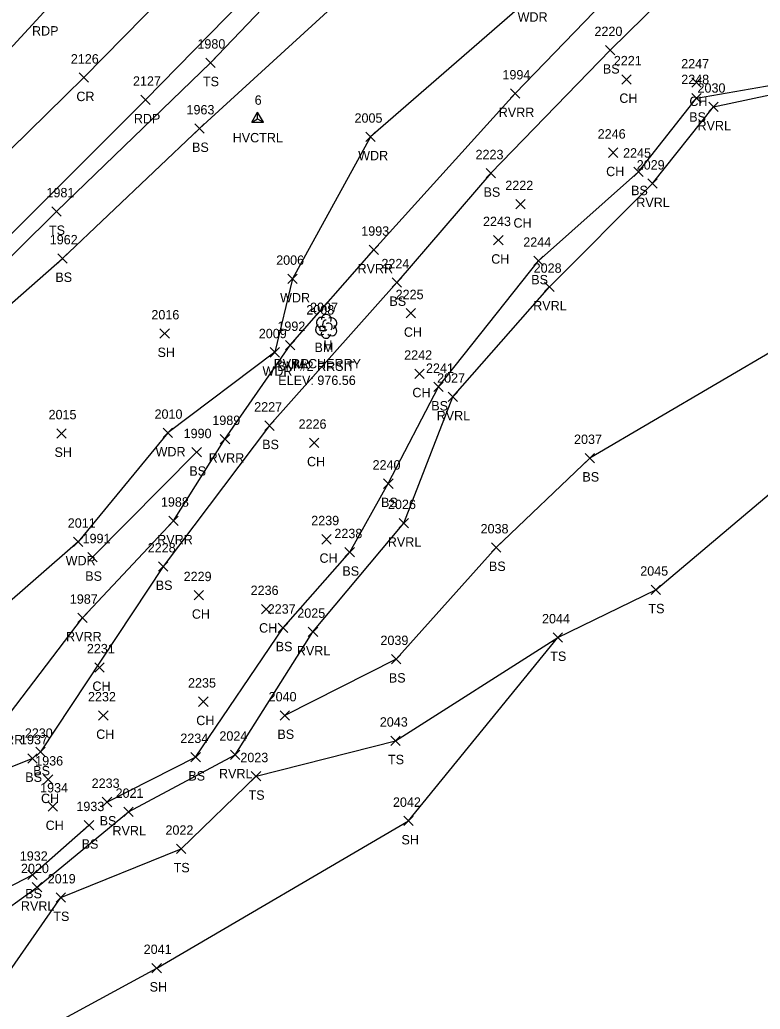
# Model space of a CAD drawing. Extents: x 1633660 to 1636532, y 388643 to 392631.
# Drawn here: x 1634615.1 to 1634772.8, y 388902.9 to 389113.6 of the extents above; entities that cross this region are included whole.
import ezdxf

# ---------------------------------------------------------------- set-up
doc = ezdxf.new("R2010")
doc.units = 0
for name, color, linetype in [('C_A', 7, 'Continuous'), ('C_C', 7, 'Continuous'), ('C_I', 7, 'Continuous'), ('CPBM', 7, 'Continuous'), ('CPSM', 7, 'Continuous'), ('L_A', 7, 'Continuous'), ('L_C', 7, 'Continuous'), ('L_I', 7, 'Continuous'), ('L_TIC', 7, 'Continuous'), ('LAWA', 7, 'Continuous'), ('LAWE', 7, 'Continuous'), ('LELB', 7, 'Continuous'), ('LSOGP', 7, 'Continuous'), ('LTD', 7, 'Continuous'), ('P_A', 7, 'Continuous'), ('P_I', 7, 'Continuous'), ('P_TIC', 7, 'Continuous'), ('PET', 7, 'Continuous'), ('PRC', 7, 'Continuous')]:
    doc.layers.add(name, color=color, linetype=linetype)

msp = doc.modelspace()

# ---------------------------------------------------------------- linework, layer by layer
at = {"layer": 'CPBM'}
for p, q in [((1634679.08, 389047.33), (1634679.08, 389048.33)), ((1634679.08, 389048.33), (1634680.08, 389048.33)), ((1634679.58, 389047.83), (1634679.58, 389047.83)), ((1634679.58, 389047.83), (1634679.58, 389047.83)), ((1634680.08, 389048.33), (1634680.08, 389047.33)), ((1634680.08, 389047.33), (1634679.08, 389047.33))]:
    msp.add_line(p, q, dxfattribs=at)
at = {"layer": 'CPSM'}
for p, q in [((1634664.53, 389091.76), (1634665.78, 389093.93)), ((1634667.03, 389091.76), (1634665.78, 389093.93)), ((1634665.79, 389092.49), (1634665.78, 389093.93)), ((1634664.53, 389091.76), (1634665.79, 389092.49)), ((1634664.53, 389091.76), (1634667.03, 389091.76)), ((1634665.79, 389092.49), (1634665.79, 389092.49)), ((1634665.79, 389092.49), (1634667.03, 389091.76))]:
    msp.add_line(p, q, dxfattribs=at)
at = {"layer": 'L_TIC'}
for points in [[(1634739.89, 389106.13), (1634741.89, 389108.13)], [(1634741.89, 389106.13), (1634739.89, 389108.13)], [(1634654.74, 389103.45), (1634656.74, 389105.45)], [(1634656.74, 389103.45), (1634654.74, 389105.45)], [(1634743.35, 389099.89), (1634745.35, 389101.89)], [(1634745.35, 389099.89), (1634743.35, 389101.89)], [(1634758.27, 389099.23), (1634760.27, 389101.23)], [(1634760.27, 389099.23), (1634758.27, 389101.23)], [(1634719.63, 389096.89), (1634721.63, 389098.89)], [(1634721.63, 389096.89), (1634719.63, 389098.89)], [(1634758.28, 389095.89), (1634760.28, 389097.89)], [(1634760.28, 389095.89), (1634758.28, 389097.89)], [(1634761.92, 389094.06), (1634763.92, 389096.06)], [(1634763.92, 389094.06), (1634761.92, 389096.06)], [(1634652.38, 389089.44), (1634654.38, 389091.44)], [(1634654.38, 389089.44), (1634652.38, 389091.44)], [(1634688.85, 389087.67), (1634690.85, 389089.67)], [(1634690.85, 389087.67), (1634688.85, 389089.67)], [(1634740.55, 389084.29), (1634742.55, 389086.29)], [(1634742.55, 389084.29), (1634740.55, 389086.29)], [(1634714.47, 389079.9), (1634716.47, 389081.9)], [(1634716.47, 389079.9), (1634714.47, 389081.9)], [(1634745.9, 389080.24), (1634747.9, 389082.24)], [(1634747.9, 389080.24), (1634745.9, 389082.24)], [(1634748.89, 389077.7), (1634750.89, 389079.7)], [(1634750.89, 389077.7), (1634748.89, 389079.7)], [(1634720.81, 389073.33), (1634722.81, 389075.33)], [(1634722.81, 389073.33), (1634720.81, 389075.33)], [(1634621.93, 389071.78), (1634623.93, 389073.78)], [(1634623.93, 389071.78), (1634621.93, 389073.78)], [(1634716.06, 389065.66), (1634718.06, 389067.66)], [(1634718.06, 389065.66), (1634716.06, 389067.66)], [(1634689.56, 389063.6), (1634691.56, 389065.6)], [(1634691.56, 389063.6), (1634689.56, 389065.6)], [(1634623.25, 389061.77), (1634625.25, 389063.77)], [(1634625.25, 389061.77), (1634623.25, 389063.77)], [(1634724.63, 389061.25), (1634726.63, 389063.25)], [(1634726.63, 389061.25), (1634724.63, 389063.25)], [(1634672.22, 389057.41), (1634674.22, 389059.41)], [(1634674.22, 389057.41), (1634672.22, 389059.41)], [(1634694.42, 389056.67), (1634696.42, 389058.67)], [(1634696.42, 389056.67), (1634694.42, 389058.67)], [(1634726.93, 389055.72), (1634728.93, 389057.72)], [(1634728.93, 389055.72), (1634726.93, 389057.72)], [(1634697.45, 389050.09), (1634699.45, 389052.09)], [(1634699.45, 389050.09), (1634697.45, 389052.09)], [(1634644.99, 389045.78), (1634646.99, 389047.78)], [(1634646.99, 389045.78), (1634644.99, 389047.78)], [(1634671.7, 389043.33), (1634673.7, 389045.33)], [(1634673.7, 389043.33), (1634671.7, 389045.33)], [(1634668.47, 389041.78), (1634670.47, 389043.78)], [(1634670.47, 389041.78), (1634668.47, 389043.78)], [(1634699.27, 389037.21), (1634701.27, 389039.21)], [(1634701.27, 389037.21), (1634699.27, 389039.21)], [(1634703.34, 389034.4), (1634705.34, 389036.4)], [(1634705.34, 389034.4), (1634703.34, 389036.4)], [(1634706.36, 389032.31), (1634708.36, 389034.31)], [(1634708.36, 389032.31), (1634706.36, 389034.31)], [(1634623.03, 389024.52), (1634625.03, 389026.52)], [(1634625.03, 389024.52), (1634623.03, 389026.52)], [(1634645.69, 389024.62), (1634647.69, 389026.62)], [(1634647.69, 389024.62), (1634645.69, 389026.62)], [(1634667.32, 389026.16), (1634669.32, 389028.16)], [(1634669.32, 389026.16), (1634667.32, 389028.16)], [(1634657.84, 389023.3), (1634659.84, 389025.3)], [(1634659.84, 389023.3), (1634657.84, 389025.3)], [(1634676.82, 389022.51), (1634678.82, 389024.51)], [(1634678.82, 389022.51), (1634676.82, 389024.51)], [(1634651.8, 389020.5), (1634653.8, 389022.5)], [(1634653.8, 389020.5), (1634651.8, 389022.5)], [(1634735.53, 389019.26), (1634737.53, 389021.26)], [(1634737.53, 389019.26), (1634735.53, 389021.26)], [(1634692.63, 389013.81), (1634694.63, 389015.81)], [(1634694.63, 389013.81), (1634692.63, 389015.81)], [(1634646.88, 389005.91), (1634648.88, 389007.91)], [(1634648.88, 389005.91), (1634646.88, 389007.91)], [(1634695.95, 389005.4), (1634697.95, 389007.4)], [(1634697.95, 389005.4), (1634695.95, 389007.4)], [(1634626.54, 389001.43), (1634628.54, 389003.43)], [(1634628.54, 389001.43), (1634626.54, 389003.43)], [(1634679.48, 389001.96), (1634681.48, 389003.96)], [(1634681.48, 389001.96), (1634679.48, 389003.96)], [(1634684.4, 388999.21), (1634686.4, 389001.21)], [(1634686.4, 388999.21), (1634684.4, 389001.21)], [(1634715.62, 389000.22), (1634717.62, 389002.22)], [(1634717.62, 389000.22), (1634715.62, 389002.22)], [(1634629.63, 388998.13), (1634631.63, 389000.13)], [(1634631.63, 388998.13), (1634629.63, 389000.13)], [(1634644.64, 388996.18), (1634646.64, 388998.18)], [(1634646.64, 388996.18), (1634644.64, 388998.18)], [(1634749.63, 388991.22), (1634751.63, 388993.22)], [(1634751.63, 388991.22), (1634749.63, 388993.22)], [(1634652.29, 388990.05), (1634654.29, 388992.05)], [(1634654.29, 388990.05), (1634652.29, 388992.05)], [(1634666.61, 388987.1), (1634668.61, 388989.1)], [(1634668.61, 388987.1), (1634666.61, 388989.1)], [(1634627.48, 388985.24), (1634629.48, 388987.24)], [(1634629.48, 388985.24), (1634627.48, 388987.24)], [(1634670.2, 388983.13), (1634672.2, 388985.13)], [(1634672.2, 388983.13), (1634670.2, 388985.13)], [(1634676.58, 388982.24), (1634678.58, 388984.24)], [(1634678.58, 388982.24), (1634676.58, 388984.24)], [(1634728.71, 388981.06), (1634730.71, 388983.06)], [(1634730.71, 388981.06), (1634728.71, 388983.06)], [(1634694.3, 388976.45), (1634696.3, 388978.45)], [(1634696.3, 388976.45), (1634694.3, 388978.45)], [(1634631.12, 388974.68), (1634633.12, 388976.68)], [(1634633.12, 388974.68), (1634631.12, 388976.68)], [(1634653.23, 388967.39), (1634655.23, 388969.39)], [(1634655.23, 388967.39), (1634653.23, 388969.39)], [(1634631.92, 388964.45), (1634633.92, 388966.45)], [(1634633.92, 388964.45), (1634631.92, 388966.45)], [(1634670.56, 388964.45), (1634672.56, 388966.45)], [(1634672.56, 388964.45), (1634670.56, 388966.45)], [(1634694.16, 388959.07), (1634696.16, 388961.07)], [(1634696.16, 388959.07), (1634694.16, 388961.07)], [(1634616.86, 388955.31), (1634618.86, 388957.31)], [(1634618.86, 388955.31), (1634616.86, 388957.31)], [(1634618.55, 388956.69), (1634620.55, 388958.69)], [(1634620.55, 388956.69), (1634618.55, 388958.69)], [(1634651.59, 388955.59), (1634653.59, 388957.59)], [(1634653.59, 388955.59), (1634651.59, 388957.59)], [(1634659.99, 388956.08), (1634661.99, 388958.08)], [(1634661.99, 388956.08), (1634659.99, 388958.08)], [(1634620.16, 388950.79), (1634622.16, 388952.79)], [(1634622.16, 388950.79), (1634620.16, 388952.79)], [(1634664.45, 388951.5), (1634666.45, 388953.5)], [(1634666.45, 388951.5), (1634664.45, 388953.5)], [(1634621.15, 388945.06), (1634623.15, 388947.06)], [(1634623.15, 388945.06), (1634621.15, 388947.06)], [(1634632.7, 388946.02), (1634634.7, 388948.02)], [(1634634.7, 388946.02), (1634632.7, 388948.02)], [(1634637.3, 388943.91), (1634639.3, 388945.91)], [(1634639.3, 388943.91), (1634637.3, 388945.91)], [(1634628.87, 388941.08), (1634630.87, 388943.08)], [(1634630.87, 388941.08), (1634628.87, 388943.08)], [(1634696.95, 388941.99), (1634698.95, 388943.99)], [(1634698.95, 388941.99), (1634696.95, 388943.99)], [(1634648.49, 388936.05), (1634650.49, 388938.05)], [(1634650.49, 388936.05), (1634648.49, 388938.05)], [(1634616.83, 388930.52), (1634618.83, 388932.52)], [(1634618.83, 388930.52), (1634616.83, 388932.52)], [(1634617.8, 388927.88), (1634619.8, 388929.88)], [(1634619.8, 388927.88), (1634617.8, 388929.88)], [(1634622.86, 388925.68), (1634624.86, 388927.68)], [(1634624.86, 388925.68), (1634622.86, 388927.68)], [(1634643.29, 388910.66), (1634645.29, 388912.66)], [(1634645.29, 388910.66), (1634643.29, 388912.66)]]:
    msp.add_lwpolyline(points, dxfattribs=at)
at = {"layer": 'LAWA'}
msp.add_lwpolyline([(1634777.74, 389176.81), (1634754.17, 389147.84), (1634723.8, 389118.19), (1634689.85, 389088.67), (1634673.22, 389058.41), (1634669.47, 389042.78), (1634646.69, 389025.62), (1634627.54, 389002.43), (1634610.06, 388987.13), (1634597.62, 388969.61)], dxfattribs=at)
at = {"layer": 'LAWE'}
for points in [[(1634485.27, 388945.87), (1634504.2, 388941.24), (1634525.53, 388940.73), (1634548.51, 388932.94), (1634584.66, 388920), (1634598.75, 388914.41), (1634618.8, 388928.88), (1634638.3, 388944.91), (1634660.99, 388957.08), (1634677.58, 388983.24), (1634696.95, 389006.4), (1634707.36, 389033.31), (1634727.93, 389056.72), (1634749.89, 389078.7), (1634762.92, 389095.06), (1634797.9, 389102.54), (1634816.33, 389112.04), (1634824.18, 389130.77), (1634824.18, 389150.65), (1634818.45, 389174.95), (1634815.05, 389205.92), (1634802.11, 389220.82), (1634788.76, 389226.82)], [(1634520.43, 388972.83), (1634529.58, 388972.39), (1634557.27, 388957.37), (1634580.07, 388955.67), (1634596.48, 388954.83), (1634611.77, 388964.29), (1634628.48, 388986.24), (1634647.88, 389006.91), (1634658.84, 389024.3), (1634672.7, 389044.33), (1634690.56, 389064.6), (1634720.63, 389097.89), (1634743.8, 389121.88), (1634765.96, 389139.81), (1634789.88, 389159.93), (1634790.78, 389168.23), (1634779.52, 389189.43), (1634780.72, 389197.89), (1634770.08, 389207.77)]]:
    msp.add_lwpolyline(points, dxfattribs=at)
at = {"layer": 'LELB'}
for points in [[(1634633.7, 388947.02), (1634652.59, 388956.59), (1634671.2, 388984.13), (1634685.4, 389000.21), (1634693.63, 389014.81), (1634704.34, 389035.4), (1634725.63, 389062.25), (1634746.9, 389081.24), (1634759.28, 389096.89), (1634788.69, 389102.01), (1634810.12, 389114.6), (1634818.92, 389123.64), (1634818.09, 389148.69), (1634815.05, 389173.41), (1634811.19, 389202.43), (1634801.32, 389217.95), (1634788.87, 389224.41)], [(1634776.58, 389212.05), (1634784.35, 389200.64), (1634784.71, 389191.5), (1634794.51, 389166.3), (1634783.97, 389147.59), (1634762.83, 389128.67), (1634740.89, 389107.13), (1634715.47, 389080.9), (1634695.42, 389057.67), (1634668.32, 389027.16), (1634645.64, 388997.18), (1634619.55, 388957.69)], [(1634531.18, 388975.28), (1634550.04, 388993.84), (1634582.85, 389016.58), (1634590.99, 389033.59), (1634624.25, 389062.77), (1634653.38, 389090.44), (1634686.4, 389120.7), (1634717.26, 389150.25), (1634744.21, 389175.48), (1634771.92, 389200.56)], [(1634703.21, 389149.54), (1634682.53, 389132.47), (1634655.74, 389104.45), (1634622.93, 389072.78), (1634589.92, 389040.08), (1634578.99, 389022.4), (1634560.52, 389008.32), (1634535.52, 388993.05), (1634511.92, 388973.77)], [(1634814.97, 389105.53), (1634790.96, 389078.59), (1634778.32, 389060.05), (1634777.25, 389044.1), (1634736.53, 389020.26), (1634716.62, 389001.22), (1634695.3, 388977.45), (1634671.56, 388965.45)], [(1634609.99, 388906.9), (1634623.86, 388926.68), (1634649.49, 388937.05), (1634665.45, 388952.5), (1634695.16, 388960.07), (1634729.71, 388982.06), (1634750.63, 388992.22), (1634777.03, 389014.48), (1634810.97, 389037.99)], [(1634652.8, 389021.5), (1634630.63, 388999.13)], [(1634617.86, 388956.31), (1634597.1, 388947.99), (1634578.19, 388950.92), (1634563.38, 388953.01), (1634537.32, 388959.95), (1634518.55, 388966.68)], [(1634486.03, 388958.42), (1634504.06, 388945.03), (1634527.82, 388945.02), (1634547.83, 388937.52), (1634559.74, 388934.65), (1634574.19, 388927.83), (1634589.05, 388923.96), (1634604.77, 388924.76), (1634617.83, 388931.52), (1634629.87, 388942.08)]]:
    msp.add_lwpolyline(points, dxfattribs=at)
at = {"layer": 'LSOGP'}
msp.add_lwpolyline([(1634218.98, 388740.85), (1634254.67, 388740.24), (1634315.25, 388739.85), (1634380.93, 388763.62), (1634394.19, 388796.15), (1634428.1, 388811.92), (1634452.29, 388827.49), (1634483.59, 388839.11), (1634515.33, 388848.44), (1634546.28, 388863.72), (1634572.45, 388876.23), (1634604.94, 388890.27), (1634644.29, 388911.66), (1634697.95, 388942.99), (1634729.71, 388982.06), (1634750.63, 388992.22), (1634777.03, 389014.48), (1634810.97, 389037.99), (1634811.65, 389038.97), (1634835.21, 389072.38), (1634837.85, 389085.95), (1634849.33, 389112.53), (1634851.42, 389137.05)], dxfattribs=at)
at = {"layer": 'LTD'}
msp.add_line((1634680.38, 389048.36), (1634680.38, 389048.36), dxfattribs=at)
msp.add_line((1634680.38, 389048.36), (1634680.38, 389048.36), dxfattribs=at)
msp.add_arc((1634680.42, 389049.8), 1.05, 335.5272, 180.9563, dxfattribs=at)
for centre, major_axis, ratio, start_param, end_param in [((1634679.59, 389049.03), (1.21, -0.51), 0.895232, 1.570796, 4.712389), ((1634680.17, 389048.82), (-0.208, -0.792), 0.645439, 3.141593, 6.283185), ((1634681.42, 389048.95), (-1.14, -0.48), 0.949671, 1.570796, 4.712389), ((1634679.29, 389047.66), (0.58, -1.04), 0.959034, 3.141593, 6.283185), ((1634679.92, 389047.61), (-0.625, -0.083), 0.423636, 0, 3.141593), ((1634680.88, 389048.2), (-0.5, 0.667), 0.989748, 3.141593, 6.283185), ((1634681.38, 389047.53), (-1.09, 0.79), 0.841452, 1.570796, 4.712389), ((1634680.38, 389046.86), (0.26, 1.06), 0.942809, 1.570796, 4.712389)]:
    msp.add_ellipse(centre, major_axis=major_axis, ratio=ratio, start_param=start_param, end_param=end_param, dxfattribs=at)
at = {"layer": 'P_TIC'}
for points in [[(1634627.75, 389100.27), (1634629.75, 389102.27)], [(1634629.75, 389100.27), (1634627.75, 389102.27)], [(1634640.93, 389095.55), (1634642.93, 389097.55)], [(1634642.93, 389095.55), (1634640.93, 389097.55)]]:
    msp.add_lwpolyline(points, dxfattribs=at)
at = {"layer": 'PET'}
msp.add_lwpolyline([(1634682.08, 389181.1), (1634650.7, 389146.38), (1634620.25, 389115.23), (1634604.63, 389098.3), (1634579.1, 389070.12), (1634546.56, 389039.3), (1634509.68, 389006.46), (1634474.11, 388976.77), (1634488.61, 388975.18), (1634504.36, 388973.04), (1634532.03, 388994.36), (1634563.21, 389020.04), (1634596.33, 389051.02), (1634641.93, 389096.55), (1634679.61, 389135.06), (1634705.94, 389161.6), (1634722.45, 389175.59), (1634749.3, 389203.85), (1634763.45, 389218.45), (1634753.18, 389229.52), (1634742.76, 389239.64), (1634704.36, 389200.19), (1634691.63, 389189.01)], dxfattribs=at)
at = {"layer": 'PRC'}
msp.add_lwpolyline([(1634489.59, 388976.11), (1634524.5, 389003.94), (1634553.65, 389029.27), (1634589.65, 389062.97), (1634628.75, 389101.27), (1634671.28, 389144.58), (1634699.51, 389173.36), (1634712.64, 389186.75), (1634739.32, 389214.16), (1634752.84, 389228.98)], dxfattribs=at)

# ---------------------------------------------------------------- texts
at = {"layer": 'C_A'}
for s, p in [('HVCTRL', (1634660.48, 389087.49)), ('BM', (1634677.9, 389042.83))]:
    msp.add_text(s, height=2, dxfattribs=at).set_placement(p)
at = {"layer": 'C_C'}
for s, p in [('BM #2 RRSIT', (1634669.98, 389038.83)), ('ELEV: 976.56', (1634670.19, 389035.83))]:
    msp.add_text(s, height=2, dxfattribs=at).set_placement(p)
at = {"layer": 'C_I'}
for s, p in [('6', (1634665.16, 389095.49)), ('2008', (1634676.16, 389050.83))]:
    msp.add_text(s, height=2, dxfattribs=at).set_placement(p)
at = {"layer": 'L_A'}
for s, p in [('WDR', (1634721.17, 389113.19)), ('BS', (1634739.33, 389102.13)), ('TS', (1634654.15, 389099.45)), ('CH', (1634742.84, 389095.89)), ('CH', (1634757.76, 389095.23)), ('RVRR', (1634717.15, 389092.89)), ('BS', (1634757.72, 389091.89)), ('RVRL', (1634759.49, 389090.06)), ('BS', (1634651.82, 389085.44)), ('WDR', (1634687.21, 389083.67)), ('CH', (1634740.03, 389080.29)), ('BS', (1634713.91, 389075.9)), ('BS', (1634745.34, 389076.24)), ('RVRL', (1634746.45, 389073.7)), ('CH', (1634720.29, 389069.33)), ('TS', (1634621.34, 389067.78)), ('CH', (1634715.55, 389061.66)), ('RVRR', (1634687.07, 389059.6)), ('BS', (1634622.7, 389057.77)), ('BS', (1634724.07, 389057.25)), ('WDR', (1634670.58, 389053.41)), ('BS', (1634693.86, 389052.67)), ('RVRL', (1634724.49, 389051.72)), ('CH', (1634696.94, 389046.09)), ('H', (1634679.81, 389043.36)), ('SH', (1634644.47, 389041.78)), ('RVRR', (1634669.21, 389039.33)), ('WDR', (1634666.83, 389037.78)), ('CH', (1634698.76, 389033.21)), ('BS', (1634702.78, 389030.4)), ('RVRL', (1634703.93, 389028.31)), ('SH', (1634622.52, 389020.52)), ('WDR', (1634644.05, 389020.62)), ('BS', (1634666.76, 389022.16)), ('RVRR', (1634655.36, 389019.3)), ('CH', (1634676.31, 389018.51)), ('BS', (1634651.24, 389016.5)), ('BS', (1634734.97, 389015.26)), ('BS', (1634692.07, 389009.81)), ('RVRR', (1634644.4, 389001.91)), ('RVRL', (1634693.52, 389001.4)), ('WDR', (1634624.9, 388997.43)), ('CH', (1634678.97, 388997.96)), ('BS', (1634683.84, 388995.21)), ('BS', (1634715.06, 388996.22)), ('BS', (1634629.07, 388994.13)), ('BS', (1634644.08, 388992.18)), ('TS', (1634749.04, 388987.22)), ('CH', (1634651.78, 388986.05)), ('CH', (1634666.1, 388983.1)), ('RVRR', (1634624.99, 388981.24)), ('BS', (1634669.64, 388979.13)), ('RVRL', (1634674.14, 388978.24)), ('TS', (1634728.12, 388977.06)), ('BS', (1634693.74, 388972.45)), ('CH', (1634630.6, 388970.68)), ('CH', (1634652.72, 388963.39)), ('RVRR', (1634608.28, 388959.29)), ('CH', (1634631.41, 388960.45)), ('BS', (1634670, 388960.45)), ('TS', (1634693.57, 388955.07)), ('BS', (1634617.99, 388952.69)), ('BS', (1634616.3, 388951.31)), ('BS', (1634651.03, 388951.59)), ('RVRL', (1634657.56, 388952.08)), ('CH', (1634619.65, 388946.79)), ('TS', (1634663.86, 388947.5)), ('CH', (1634620.64, 388941.06)), ('BS', (1634632.14, 388942.02)), ('RVRL', (1634634.87, 388939.91)), ('SH', (1634696.43, 388937.99)), ('BS', (1634628.31, 388937.08)), ('TS', (1634647.9, 388932.05)), ('BS', (1634616.27, 388926.52)), ('RVRL', (1634615.37, 388923.88)), ('TS', (1634622.27, 388921.68)), ('SH', (1634642.78, 388906.66))]:
    msp.add_text(s, height=2, dxfattribs=at).set_placement(p)
at = {"layer": 'L_C'}
msp.add_text('M.CHERRY', height=2, dxfattribs=at).set_placement((1634673.56, 389039.36))
at = {"layer": 'L_I'}
for s, p in [('2220', (1634737.54, 389110.13)), ('1980', (1634652.96, 389107.45)), ('2221', (1634741.66, 389103.89)), ('2247', (1634756.01, 389103.23)), ('1994', (1634717.94, 389100.89)), ('2248', (1634756.02, 389099.89)), ('2030', (1634759.49, 389098.06)), ('1963', (1634650.64, 389093.44)), ('2005', (1634686.43, 389091.67)), ('2246', (1634738.23, 389088.29)), ('2223', (1634712.21, 389083.9)), ('2245', (1634743.64, 389084.24)), ('2029', (1634746.54, 389081.7)), ('2222', (1634718.55, 389077.33)), ('1981', (1634620.81, 389075.78)), ('2243', (1634713.8, 389069.66)), ('1993', (1634687.86, 389067.6)), ('1962', (1634621.51, 389065.77)), ('2244', (1634722.37, 389065.25)), ('2006', (1634669.74, 389061.41)), ('2224', (1634692.16, 389060.67)), ('2028', (1634724.59, 389059.72)), ('2225', (1634695.19, 389054.09)), ('2016', (1634643.16, 389049.78)), ('2007', (1634676.96, 389051.36)), ('2009', (1634666.04, 389045.78)), ('1992', (1634670, 389047.33)), ('2242', (1634697.01, 389041.21)), ('2241', (1634701.65, 389038.4)), ('2027', (1634704.03, 389036.31)), ('2010', (1634643.83, 389028.62)), ('2227', (1634665.06, 389030.16)), ('2015', (1634621.26, 389028.52)), ('1989', (1634656.14, 389027.3)), ('2226', (1634674.51, 389026.51)), ('1990', (1634650.02, 389024.5)), ('2037', (1634733.19, 389023.26)), ('2240', (1634690.28, 389017.81)), ('1988', (1634645.19, 389009.91)), ('2026', (1634693.56, 389009.4)), ('2011', (1634625.34, 389005.43)), ('2239', (1634677.21, 389005.96)), ('2038', (1634713.28, 389004.22)), ('1991', (1634628.5, 389002.13)), ('2238', (1634682.14, 389003.21)), ('2228', (1634642.38, 389000.18)), ('2045', (1634747.29, 388995.22)), ('2229', (1634650.03, 388994.05)), ('2236', (1634664.3, 388991.1)), ('1987', (1634625.79, 388989.24)), ('2237', (1634667.94, 388987.13)), ('2025', (1634674.24, 388986.24)), ('2044', (1634726.37, 388985.06)), ('2039', (1634691.95, 388980.45)), ('2231', (1634629.42, 388978.68)), ('2235', (1634650.97, 388971.39)), ('2232', (1634629.66, 388968.45)), ('2040', (1634668.13, 388968.45)), ('2043', (1634691.82, 388963.07)), ('1937', (1634615.17, 388959.31)), ('2230', (1634616.2, 388960.69)), ('2234', (1634649.33, 388959.59)), ('2024', (1634657.65, 388960.08)), ('1936', (1634618.41, 388954.79)), ('2023', (1634662.11, 388955.5)), ('1934', (1634619.46, 388949.06)), ('2233', (1634630.44, 388950.02)), ('2021', (1634635.53, 388947.91)), ('1933', (1634627.18, 388945.08)), ('2042', (1634694.61, 388945.99)), ('2022', (1634646.16, 388940.05)), ('1932', (1634615.13, 388934.52)), ('2020', (1634615.38, 388931.88)), ('2019', (1634621.08, 388929.68)), ('2041', (1634641.52, 388914.66))]:
    msp.add_text(s, height=2, dxfattribs=at).set_placement(p)
at = {"layer": 'P_A'}
for s, p in [('RDP', (1634617.73, 389110.23)), ('CR', (1634627.18, 389096.27)), ('RDP', (1634639.42, 389091.55))]:
    msp.add_text(s, height=2, dxfattribs=at).set_placement(p)
at = {"layer": 'P_I'}
for s, p in [('2126', (1634626, 389104.27)), ('2127', (1634639.24, 389099.55))]:
    msp.add_text(s, height=2, dxfattribs=at).set_placement(p)

doc.saveas('drawing.dxf')
